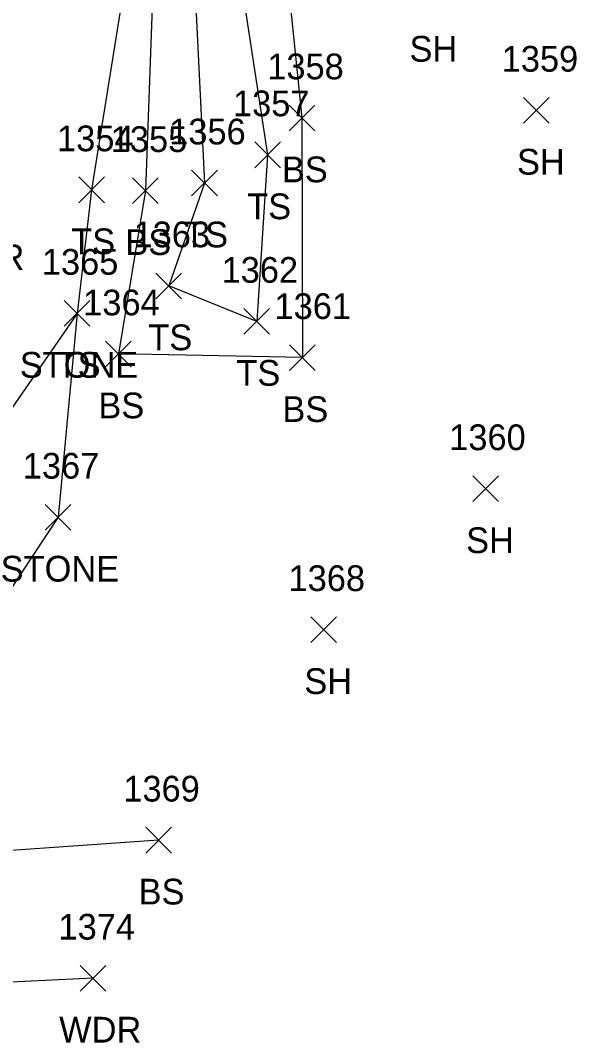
# Model space of a CAD drawing. Extents: x 1618262 to 1622220, y 273782 to 283685.
# Drawn here: x 1622140.8 to 1622184, y 282679.3 to 282758.7 of the extents above; entities that cross this region are included whole.
import ezdxf

# ---------------------------------------------------------------- set-up
doc = ezdxf.new("R2010")
doc.units = 0
for name, color, linetype in [('L_A', 7, 'Continuous'), ('L_I', 7, 'Continuous'), ('L_TIC', 7, 'Continuous'), ('LASF', 7, 'Continuous'), ('LAWA', 7, 'Continuous'), ('LELB', 7, 'Continuous')]:
    doc.layers.add(name, color=color, linetype=linetype)

msp = doc.modelspace()

# ---------------------------------------------------------------- linework, layer by layer
at = {"layer": 'L_TIC'}
for points in [[(1622179.881, 282750.761), (1622181.881, 282752.761)], [(1622181.881, 282750.761), (1622179.881, 282752.761)], [(1622161.643, 282750.166), (1622163.643, 282752.166)], [(1622163.643, 282750.166), (1622161.643, 282752.166)], [(1622158.979, 282747.296), (1622160.979, 282749.296)], [(1622160.979, 282747.296), (1622158.979, 282749.296)], [(1622154.071, 282745.106), (1622156.071, 282747.106)], [(1622156.071, 282745.106), (1622154.071, 282747.106)], [(1622145.295, 282744.577), (1622147.295, 282746.577)], [(1622147.295, 282744.577), (1622145.295, 282746.577)], [(1622149.472, 282744.517), (1622151.472, 282746.517)], [(1622151.472, 282744.517), (1622149.472, 282746.517)], [(1622151.292, 282737.115), (1622153.292, 282739.115)], [(1622153.292, 282737.115), (1622151.292, 282739.115)], [(1622151.292, 282737.115), (1622153.292, 282739.115)], [(1622153.292, 282737.115), (1622151.292, 282739.115)], [(1622144.163, 282734.978), (1622146.163, 282736.978)], [(1622146.163, 282734.978), (1622144.163, 282736.978)], [(1622144.163, 282734.978), (1622146.163, 282736.978)], [(1622146.163, 282734.978), (1622144.163, 282736.978)], [(1622158.136, 282734.354), (1622160.136, 282736.354)], [(1622160.136, 282734.354), (1622158.136, 282736.354)], [(1622147.376, 282731.824), (1622149.376, 282733.824)], [(1622149.376, 282731.824), (1622147.376, 282733.824)], [(1622147.376, 282731.824), (1622149.376, 282733.824)], [(1622149.376, 282731.824), (1622147.376, 282733.824)], [(1622161.686, 282731.538), (1622163.686, 282733.538)], [(1622163.686, 282731.538), (1622161.686, 282733.538)], [(1622175.924, 282721.348), (1622177.924, 282723.348)], [(1622177.924, 282721.348), (1622175.924, 282723.348)], [(1622142.678, 282719.136), (1622144.678, 282721.136)], [(1622144.678, 282719.136), (1622142.678, 282721.136)], [(1622163.344, 282710.399), (1622165.344, 282712.399)], [(1622165.344, 282710.399), (1622163.344, 282712.399)], [(1622150.504, 282694.042), (1622152.504, 282696.042)], [(1622152.504, 282694.042), (1622150.504, 282696.042)], [(1622145.408, 282683.313), (1622147.408, 282685.313)], [(1622147.408, 282683.313), (1622145.408, 282685.313)]]:
    msp.add_lwpolyline(points, dxfattribs=at)
at = {"layer": 'LASF'}
msp.add_lwpolyline([(1622145.163, 282735.978), (1622143.678, 282720.136), (1622134.988, 282707.013), (1622124.116, 282693.112), (1622102.742, 282693.292), (1622097.849, 282695.719), (1622096.809, 282706.041), (1622095.152, 282712.05), (1622094.742, 282720.999), (1622098.882, 282731.605), (1622115.268, 282742.964)], dxfattribs=at)
at = {"layer": 'LAWA'}
msp.add_lwpolyline([(1622146.408, 282684.313), (1622111.705, 282682.621), (1622100.241, 282683.651), (1622096.674, 282685.998), (1622097.849, 282695.719)], dxfattribs=at)
at = {"layer": 'LELB'}
for points in [[(1622157.901, 282795.316), (1622151.518, 282778.21), (1622146.295, 282745.577), (1622145.163, 282735.978), (1622131.784, 282716.638), (1622123.793, 282704.55), (1622117.42, 282698.441), (1622102.742, 282693.292)], [(1622157.862, 282774.252), (1622151.37, 282769.816), (1622150.472, 282745.517), (1622148.376, 282732.824)], [(1622157.862, 282774.252), (1622161.195, 282765.354), (1622162.643, 282751.166), (1622162.686, 282732.538), (1622148.376, 282732.824)], [(1622154.08, 282766.145), (1622155.071, 282746.106), (1622152.292, 282738.115)], [(1622154.08, 282766.145), (1622157.504, 282764.419), (1622159.979, 282748.296), (1622159.136, 282735.354), (1622152.292, 282738.115)], [(1622151.504, 282695.042), (1622124.116, 282693.112)]]:
    msp.add_lwpolyline(points, dxfattribs=at)

# ---------------------------------------------------------------- texts
at = {"layer": 'L_A'}
for s, p in [('SH', (1622171.013, 282755.537)), ('SH', (1622179.369, 282746.761)), ('BS', (1622161.084, 282746.166)), ('TS', (1622158.389, 282743.296)), ('TS', (1622153.481, 282741.106)), ('TS', (1622144.704, 282740.577)), ('BS', (1622148.913, 282740.517)), ('BRKR', (1622133.629, 282739.352)), ('TS', (1622150.701, 282733.115)), ('TS', (1622150.701, 282733.115)), ('STONE', (1622140.706, 282730.978)), ('TS', (1622143.572, 282730.978)), ('TS', (1622157.545, 282730.354)), ('BS', (1622146.817, 282727.824)), ('BS', (1622146.817, 282727.824)), ('BS', (1622161.127, 282727.538)), ('SH', (1622175.413, 282717.348)), ('STONE', (1622139.221, 282715.136)), ('SH', (1622162.832, 282706.399)), ('BS', (1622149.945, 282690.042)), ('WDR', (1622143.771, 282679.313))]:
    msp.add_text(s, height=2, dxfattribs=at).set_placement(p)
at = {"layer": 'L_I'}
for s, p in [('1359', (1622178.181, 282754.761)), ('1358', (1622159.95, 282754.166)), ('1357', (1622157.287, 282751.296)), ('1356', (1622152.324, 282749.106)), ('1354', (1622143.602, 282748.577)), ('1355', (1622147.78, 282748.517)), ('1363', (1622149.552, 282741.115)), ('1363', (1622149.552, 282741.115)), ('1365', (1622142.423, 282738.978)), ('1365', (1622142.423, 282738.978)), ('1362', (1622156.396, 282738.354)), ('1364', (1622145.636, 282735.824)), ('1364', (1622145.636, 282735.824)), ('1361', (1622160.513, 282735.538)), ('1360', (1622174.098, 282725.348)), ('1367', (1622140.938, 282723.136)), ('1368', (1622161.604, 282714.399)), ('1369', (1622148.757, 282698.042)), ('1374', (1622143.716, 282687.313))]:
    msp.add_text(s, height=2, dxfattribs=at).set_placement(p)

doc.saveas('drawing.dxf')
